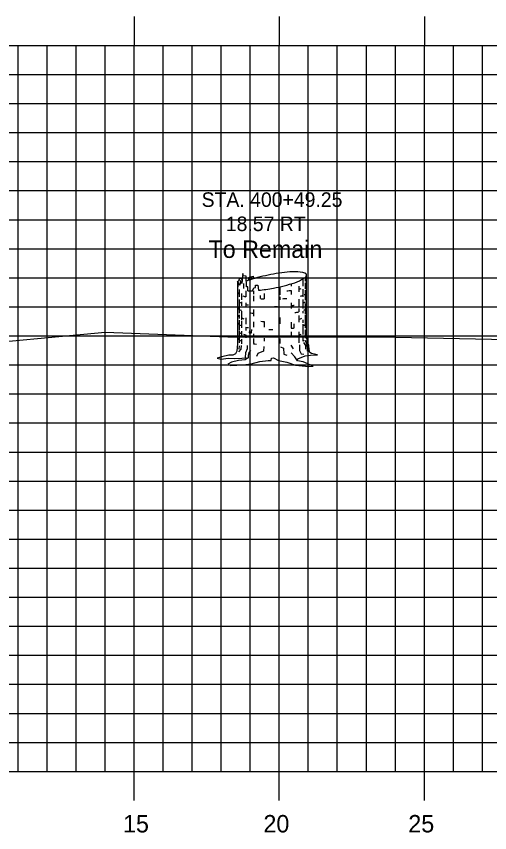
# Model space of a CAD drawing. Extents: x -161 to 764, y 111 to 210.
# Drawn here: x 165.11 to 181.42, y 125.06 to 153.17 of the extents above; entities that cross this region are included whole.
import ezdxf

# ---------------------------------------------------------------- set-up
doc = ezdxf.new("R2010")
doc.units = 0
for name, color, linetype in [('D_Text_Monospaced', 7, 'Continuous'), ('D_Text_Standard', 7, 'Continuous'), ('H_V ANNOTATION', 7, 'Continuous'), ('MAJOR', 7, 'Continuous'), ('MINOR', 7, 'Continuous'), ('S_Roadway_Centerline', 7, 'Continuous'), ('S_Trees_Decid_Pay', 7, 'Continuous')]:
    doc.layers.add(name, color=color, linetype=linetype)

msp = doc.modelspace()

# ---------------------------------------------------------------- linework, layer by layer
at = {"layer": 'MAJOR'}
for p, q in [((169.168, 153.171), (169.168, 152.169)), ((174.168, 153.171), (174.168, 152.169)), ((179.168, 153.171), (179.168, 152.169)), ((84.168, 152.169), (224.168, 152.169)), ((84.168, 152.169), (224.168, 152.169)), ((169.168, 127.169), (169.168, 152.169)), ((174.168, 127.169), (174.168, 152.169)), ((179.168, 127.169), (179.168, 152.169)), ((84.168, 147.169), (224.168, 147.169)), ((84.168, 142.169), (224.168, 142.169)), ((84.168, 137.169), (224.168, 137.169)), ((84.168, 132.169), (224.168, 132.169)), ((84.168, 127.169), (224.168, 127.169)), ((84.168, 127.169), (224.168, 127.169)), ((169.168, 126.167), (169.168, 127.169)), ((174.168, 126.167), (174.168, 127.169)), ((179.168, 126.167), (179.168, 127.169))]:
    msp.add_line(p, q, dxfattribs=at)
at = {"layer": 'MINOR'}
for p, q in [((165.168, 127.169), (165.168, 152.169)), ((166.168, 127.169), (166.168, 152.169)), ((167.168, 127.169), (167.168, 152.169)), ((168.168, 127.169), (168.168, 152.169)), ((170.168, 127.169), (170.168, 152.169)), ((171.168, 127.169), (171.168, 152.169)), ((172.168, 127.169), (172.168, 152.169)), ((173.168, 127.169), (173.168, 152.169)), ((175.168, 127.169), (175.168, 152.169)), ((176.168, 127.169), (176.168, 152.169)), ((177.168, 127.169), (177.168, 152.169)), ((178.168, 127.169), (178.168, 152.169)), ((180.168, 127.169), (180.168, 152.169)), ((181.168, 127.169), (181.168, 152.169)), ((84.168, 151.169), (224.168, 151.169)), ((84.168, 150.169), (224.168, 150.169)), ((84.168, 149.169), (224.168, 149.169)), ((84.168, 148.169), (224.168, 148.169)), ((84.168, 146.169), (224.168, 146.169)), ((84.168, 145.169), (224.168, 145.169)), ((84.168, 144.169), (224.168, 144.169)), ((84.168, 143.169), (224.168, 143.169)), ((84.168, 141.169), (224.168, 141.169)), ((84.168, 140.169), (224.168, 140.169)), ((84.168, 139.169), (224.168, 139.169)), ((84.168, 138.169), (224.168, 138.169)), ((84.168, 136.169), (224.168, 136.169)), ((84.168, 135.169), (224.168, 135.169)), ((84.168, 134.169), (224.168, 134.169)), ((84.168, 133.169), (224.168, 133.169)), ((84.168, 131.169), (224.168, 131.169)), ((84.168, 130.169), (224.168, 130.169)), ((84.168, 129.169), (224.168, 129.169)), ((84.168, 128.169), (224.168, 128.169))]:
    msp.add_line(p, q, dxfattribs=at)
at = {"layer": 'S_Roadway_Centerline'}
msp.add_lwpolyline([(152.685, 140.854), (168.169, 142.293), (172.399, 142.133), (178.178, 142.122), (186.449, 141.953), (186.572, 141.953), (199.915, 140.445), (200.903, 140.058), (203.287, 137.833), (209.093, 136.316), (210.852, 135.055), (224.168, 133.439)], dxfattribs=at)
at = {"layer": 'S_Trees_Decid_Pay'}
for p, q in [((172.933, 143.968), (172.933, 143.794)), ((174.573, 143.96), (174.573, 143.874)), ((174.978, 144.127), (174.978, 143.874)), ((175.058, 144.172), (175.058, 144.051)), ((175.058, 143.999), (175.058, 143.785)), ((172.784, 143.768), (172.784, 143.514)), ((173.018, 143.72), (173.018, 143.515)), ((173.279, 143.722), (173.279, 143.602)), ((174.19, 143.859), (174.19, 143.579)), ((174.573, 143.733), (174.573, 143.594)), ((174.845, 143.874), (174.845, 143.682)), ((174.978, 143.777), (174.978, 143.514)), ((175.058, 143.74), (175.058, 143.402)), ((172.784, 143.416), (172.784, 142.947)), ((172.87, 143.622), (172.87, 143.411)), ((173.279, 143.55), (173.279, 143.365)), ((173.517, 143.45), (173.522, 143.557)), ((173.644, 143.622), (173.644, 143.443)), ((174.19, 143.514), (174.19, 143.411)), ((174.845, 143.431), (174.845, 143.153)), ((174.978, 143.416), (174.978, 143.108)), ((172.87, 143.345), (172.87, 143.197)), ((173.018, 143.308), (173.018, 143.153)), ((174.573, 143.308), (174.573, 143.116)), ((174.845, 143.108), (174.845, 142.999)), ((175.058, 143.285), (175.058, 142.924)), ((172.784, 142.896), (172.784, 142.762)), ((172.87, 143.019), (172.87, 142.719)), ((173.279, 143.079), (173.279, 142.851)), ((174.845, 142.865), (174.845, 142.636)), ((174.978, 143.019), (174.978, 142.953)), ((175.058, 142.888), (175.058, 142.439)), ((172.784, 142.704), (172.784, 142.379)), ((172.87, 142.682), (172.87, 142.439)), ((173.018, 142.79), (173.018, 142.571)), ((173.279, 142.653), (173.279, 142.468)), ((173.644, 142.664), (173.644, 142.468)), ((174.19, 142.799), (174.19, 142.579)), ((174.573, 142.636), (174.573, 142.428)), ((174.978, 142.719), (174.978, 142.622)), ((174.978, 142.571), (174.978, 142.21)), ((172.784, 142.35), (172.784, 141.93)), ((172.87, 142.328), (172.87, 142.187)), ((173.018, 142.471), (173.018, 142.35)), ((174.573, 142.307), (174.573, 142.107)), ((174.845, 142.307), (174.845, 141.924)), ((175.058, 142.373), (175.058, 142.091)), ((172.87, 142.056), (172.87, 141.899)), ((173.018, 142.199), (173.018, 142.101)), ((173.279, 142.233), (173.279, 142.156)), ((173.279, 142.079), (173.279, 141.905)), ((173.644, 142.084), (173.644, 141.981)), ((174.19, 142.079), (174.19, 141.905)), ((174.978, 142.159), (174.978, 141.992)), ((172.787, 141.827), (172.772, 141.71)), ((174.568, 141.85), (174.648, 141.718))]:
    msp.add_line(p, q, dxfattribs=at)
for points in [[(172.733, 144.042), (172.733, 141.905), (172.713, 141.764), (172.707, 141.638), (172.663, 141.551), (172.571, 141.502), (172.435, 141.502), (172.192, 141.446), (172.025, 141.397), (172.167, 141.366), (172.404, 141.403), (172.614, 141.391), (172.875, 141.397), (172.999, 141.415), (173.03, 141.372), (173.092, 141.415), (172.993, 141.348), (172.758, 141.323), (172.528, 141.261), (172.398, 141.191), (172.497, 141.147), (172.919, 141.166), (173.197, 141.21), (173.496, 141.286), (173.782, 141.323), (173.887, 141.323), (173.905, 141.403), (173.973, 141.409), (174.14, 141.323), (174.426, 141.267), (174.725, 141.16), (175.184, 141.111), (175.338, 141.123), (174.996, 141.273), (174.793, 141.304), (174.805, 141.378), (175.064, 141.477), (175.24, 141.508), (175.48, 141.52), (175.282, 141.558), (175.221, 141.594), (175.196, 141.681), (175.184, 141.85), (175.139, 141.936), (175.11, 142.177), (175.11, 144.263)], [(173.089, 143.715), (173.081, 143.859), (173.036, 143.851), (173.022, 144.226), (172.927, 144.234), (172.913, 144.314), (172.875, 143.977), (172.83, 144.071), (172.81, 143.917), (172.733, 144.042), (172.739, 143.853)], [(173.112, 144.081), (173.133, 144.189), (173.265, 144.22), (173.272, 144.132)], [(172.733, 144.042), (172.779, 144.065), (172.801, 144.131), (172.853, 144.154), (172.887, 144.079)], [(173.251, 143.72), (173.288, 143.823), (173.353, 143.829), (173.353, 143.911), (173.427, 143.917), (173.452, 143.737)], [(174.686, 142.442), (174.685, 142.519), (174.677, 142.585)], [(173.141, 142.35), (173.133, 142.276), (173.207, 142.27), (173.221, 142.387)], [(175.06, 142.019), (175.12, 141.858), (175.134, 141.733), (175.126, 141.636)], [(172.853, 141.835), (172.847, 141.71), (172.765, 141.615)], [(172.999, 141.415), (173.018, 141.594), (173.079, 141.731), (173.073, 141.831)], [(173.642, 141.798), (173.625, 141.644), (173.427, 141.563), (173.382, 141.46)], [(174.207, 141.79), (174.31, 141.739), (174.325, 141.533), (174.428, 141.504)], [(174.862, 141.864), (174.862, 141.659), (174.92, 141.549), (175.017, 141.533)], [(175.003, 141.938), (175.074, 141.835), (175.074, 141.71)], [(173.19, 141.663), (173.116, 141.594), (173.098, 141.496), (173.092, 141.415)], [(174.793, 141.304), (174.706, 141.446), (174.574, 141.588)]]:
    msp.add_lwpolyline(points, dxfattribs=at)
for centre, radius, start, end in [((175.023, 138.261), 6.126, 100.7779, 107.8613), ((175.023, 138.261), 6.126, 93.6944, 100.7779), ((174.712, 143.078), 1.299, 78.2779, 93.6944), ((174.879, 143.881), 0.48, 69.9843, 78.2779), ((174.987, 144.177), 0.164, 55.7779, 69.9843), ((174.96, 144.315), 0.164, 311.5714, 325.7779), ((175.018, 144.224), 0.107, 45.9547, 55.7779), ((175.048, 144.255), 0.0645, 33.2779, 45.9547), ((175.007, 144.283), 0.107, 325.7779, 335.6011), ((175.057, 144.26), 0.0544, 22.46, 33.2779), ((175.046, 144.265), 0.0645, 335.6011, 348.2779), ((175.064, 144.263), 0.0467, 10.7779, 22.46), ((175.056, 144.263), 0.0544, 348.2779, 359.0957), ((175.064, 144.263), 0.0467, 359.0957, 10.7779), ((173.543, 142.855), 1.299, 107.8613, 113.3069), ((172.821, 149.83), 6.126, 280.7779, 287.8613), ((174.301, 145.236), 1.299, 287.8613, 303.2779), ((174.751, 144.551), 0.48, 303.2779, 311.5714), ((172.781, 143.674), 0.0476, 180, 191.6815), ((172.789, 143.676), 0.0554, 191.6815, 202.5), ((172.798, 143.68), 0.0657, 202.5, 215.1737), ((173.132, 145.014), 1.299, 268.1289, 273.6944), ((172.821, 149.83), 6.126, 273.6944, 274.0246), ((172.821, 149.83), 6.126, 275.9147, 280.7779), ((173.923, 149.613), 5.916, 274.9514, 276.3087), ((174.499, 145.025), 1.292, 285.5651, 289.0916), ((174.971, 144.006), 0.166, 301.67, 315), ((175.011, 143.965), 0.109, 315, 324.8263), ((175.046, 143.68), 0.0657, 324.8263, 337.5), ((175.047, 143.94), 0.0657, 324.8263, 337.5), ((175.055, 143.676), 0.0554, 337.5, 348.3185), ((175.056, 143.936), 0.0554, 337.5, 348.3185), ((172.834, 143.705), 0.109, 215.1737, 225), ((172.874, 143.745), 0.166, 225, 239.1924), ((173.346, 144.764), 1.292, 250.6119, 255.2856), ((173.922, 149.352), 5.916, 266.0776, 267.3043), ((173.922, 149.352), 5.916, 273.5382, 274.8924), ((174.498, 144.764), 1.292, 288.0829, 292.5), ((174.807, 144.018), 0.484, 297.4162, 300.8076), ((174.97, 143.745), 0.166, 300.8076, 315), ((175.01, 143.705), 0.109, 315, 324.8263), ((172.781, 143.153), 0.0476, 180, 191.6815), ((172.789, 143.155), 0.0554, 191.6815, 202.5), ((172.798, 143.159), 0.0657, 202.5, 215.1737), ((172.834, 143.184), 0.109, 215.1737, 225), ((172.874, 143.224), 0.166, 225, 239.1924), ((172.874, 143.482), 0.166, 237.0378, 239.1924), ((173.037, 143.755), 0.484, 239.1924, 247.5), ((173.346, 144.501), 1.292, 247.5, 248.3537), ((173.346, 144.501), 1.292, 255.2856, 259.2632), ((173.922, 149.089), 5.916, 270.1162, 271.7708), ((173.922, 149.089), 5.916, 276.3183, 277.1546), ((174.498, 144.501), 1.292, 277.1546, 278.3662), ((174.498, 144.501), 1.292, 291.8071, 292.5), ((174.807, 143.755), 0.484, 292.5, 300.8076), ((174.97, 143.482), 0.166, 300.8076, 301.6001), ((174.97, 143.224), 0.166, 300.8076, 315), ((175.01, 143.184), 0.109, 315, 324.8263), ((175.046, 143.159), 0.0657, 324.8263, 337.5), ((175.055, 143.155), 0.0554, 337.5, 348.3185), ((172.781, 142.896), 0.0476, 180, 191.6815), ((172.789, 142.897), 0.0554, 191.6815, 202.5), ((172.798, 142.901), 0.0657, 202.5, 215.1737), ((172.834, 142.926), 0.109, 215.1737, 225), ((172.874, 142.967), 0.166, 225, 239.1924), ((173.037, 143.497), 0.484, 239.1924, 245.7724), ((173.346, 144.243), 1.292, 247.5, 248.4842), ((173.346, 144.243), 1.292, 261.8726, 262.8454), ((173.922, 148.831), 5.916, 262.8454, 263.7595), ((174.498, 144.243), 1.292, 279.2565, 285.6105), ((174.807, 143.497), 0.484, 294.6372, 300.8076), ((174.97, 142.967), 0.166, 302.0694, 315), ((175.01, 142.926), 0.109, 315, 324.8263), ((175.046, 142.901), 0.0657, 324.8263, 337.5), ((175.055, 142.897), 0.0554, 337.5, 348.3185), ((172.781, 142.63), 0.0476, 180, 191.6815), ((172.789, 142.632), 0.0554, 191.6815, 202.5), ((172.798, 142.636), 0.0657, 202.5, 215.1737), ((172.834, 142.661), 0.109, 215.1737, 225), ((172.874, 142.701), 0.166, 225, 239.1924), ((173.037, 142.974), 0.484, 239.1924, 247.5), ((173.346, 143.986), 1.292, 247.5, 251.799), ((173.346, 143.721), 1.292, 247.5, 248.3537), ((173.922, 148.574), 5.916, 266.2721, 267.3043), ((174.498, 143.986), 1.292, 285.6105, 290.1001), ((174.807, 142.974), 0.484, 292.5, 300.8076), ((174.97, 142.701), 0.166, 300.8076, 302.0694), ((175.055, 142.632), 0.0554, 337.5, 348.3185), ((173.037, 142.702), 0.484, 242.734, 247.5), ((173.346, 143.721), 1.292, 255.2856, 259.2463), ((173.922, 148.308), 5.916, 268.9206, 270), ((173.922, 148.308), 5.916, 270, 270.2757), ((173.922, 148.308), 5.916, 276.3183, 277.1546), ((174.498, 143.721), 1.292, 277.1546, 278.3795), ((174.97, 142.429), 0.166, 302.0694, 315), ((175.01, 142.389), 0.109, 315, 324.8263), ((175.046, 142.364), 0.0657, 324.8263, 337.5), ((175.055, 142.36), 0.0554, 337.5, 348.3185), ((172.781, 142.101), 0.0476, 180, 191.6815), ((172.789, 142.103), 0.0554, 191.6815, 202.5), ((172.798, 142.107), 0.0657, 202.5, 215.1737), ((172.834, 142.132), 0.109, 215.1737, 225), ((172.874, 142.172), 0.166, 225, 239.1924), ((173.037, 142.445), 0.484, 239.1924, 247.5), ((173.346, 143.191), 1.292, 247.5, 248.3537), ((173.346, 143.449), 1.292, 251.3664, 255.2856), ((173.922, 148.037), 5.916, 273.2637, 274.461), ((173.922, 148.037), 5.916, 276.3183, 277.1546), ((174.498, 143.449), 1.292, 277.1546, 278.3662), ((174.498, 143.449), 1.292, 285.6105, 289.1534), ((174.507, 143.195), 1.292, 291.3696, 292.0604), ((174.807, 142.445), 0.484, 292.5, 296.5499), ((173.922, 147.779), 5.916, 263.7831, 264.7655)]:
    msp.add_arc(centre, radius, start, end, dxfattribs=at)

# ---------------------------------------------------------------- texts
at = {"layer": 'D_Text_Monospaced'}
for s, height, p in [('STA. 400+49.25', 0.49998, (171.493, 146.61)), ('18.57 RT', 0.5, (172.327, 145.776))]:
    msp.add_text(s, height=height, dxfattribs=at).set_placement(p)
at = {"layer": 'D_Text_Standard'}
msp.add_text('To Remain', height=0.6, dxfattribs=at).set_placement((171.729, 144.852))
at = {"layer": 'H_V ANNOTATION'}
for s, p in [('15', (168.785, 125.069)), ('20', (173.622, 125.069)), ('25', (178.614, 125.069))]:
    msp.add_text(s, height=0.6, rotation=360, dxfattribs=at).set_placement(p)

doc.saveas('drawing.dxf')
